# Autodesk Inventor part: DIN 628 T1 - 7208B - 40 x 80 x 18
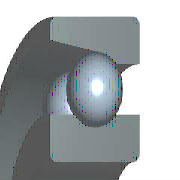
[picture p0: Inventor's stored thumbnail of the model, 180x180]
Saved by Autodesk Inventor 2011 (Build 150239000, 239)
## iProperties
IsCustomPart: 0
Created: 2009-02
Part Number: DIN 628 T1 - 7208B - 40 x 80 x 18
Material: Steel, Mild
Description: Angular Contact Ball Bearing
Document SubType Name: Modeling
Standard: DIN 628 T1
Designer: 904Chiaki
Standards Organization: DIN
Language: en-US
Size Designation: 7208B - 40 x 80 x 18
Categories: <MemberInstance><Categories><Category DisplayName="Shaft Parts" InternalName="7f7aeb1f-a693-4053-b835-cee3144e0d98" Mnemonic="SHFT"><Category DisplayName="Beari
Density: 1 g/cm^3
Author: 904Chiaki
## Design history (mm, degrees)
revolve "Body" stored, may be unused: angle "d9" = 90 deg
revolve "Ball" stored, may be unused: angle "d12" = 90 deg
pattern_circular "Balls" dims angle "d2" = 360 deg
body "Solid1"
sketch "Sketch" dims "d3" = 11.6 (= DDB)
  geometry: L1 (9, 24.2)-(9, 35.8); L2 (5.52, 34.64)-(0, 34.64); L3 (4.36, 26.52)-(0, 26.52); L4 (0, 20)-(18, 20); L5 (0, 40)-(18, 40); L6 (18, 20)-(18, 25.36); L7 (18, 33.48)-(18, 40); L8 (13.64, 33.48)-(18, 33.48); L9 (12.48, 25.36)-(18, 25.36); L10 (9, 30)-(14.8, 30); L11 (9, 30)-(3.2, 30); L12 (-3.6, 0)-(21.6, 0) reference; L13 (0, -3.4)-(0, 23.9) reference
  constraints: 22 end point, 4 point on line, 3 parallel, 2 perpendicular, 2 symmetric about line, 1 collinear, 1 midpoint, 10 other
  dimensions: "d8" = 53.04 diameter of L3 L12 (= KID1); "d10" = 40 diameter of L4 L12 (= WD); "d11" = 60 diameter of L10.start L12 (= DDA); "d13" = 69.28 diameter of L2 L12 (= DBB); "d15" = 50.72 diameter of L9 L12 (= DAC); "d16" = 66.96 diameter of L8 L12 (= KAD1); "d17" = 80 diameter of L5 L12 (= BD); "d18" = 18 distance between parallel lines of L13 L6 (= KB)
fillet "Fillet1" dims "d0" = 1.1 (= KRS), "d4" = 0.6 (= KR1S)
other parameters: "WD" = 40 [user parameter; used in 2 equation terms], "BD" = 80 [user parameter; used in 2 equation terms], "KB" = 18 [user parameter; used in 1 equation term], "KRS" = 1.1 [user parameter; used in 1 equation term], "KR1S" = 0.6 [user parameter; used in 1 equation term], "KID1" = 53.04 [user parameter; used in 1 equation term], "DAC" = 50.72 [user parameter; used in 1 equation term], "KAD1" = 66.96 [user parameter; used in 1 equation term], "DBB" = 69.28 [user parameter; used in 1 equation term], "DDA" = 60 [user parameter; used in 2 equation terms], "DDB" = 11.6 [user parameter; used in 2 equation terms], "d5" = 0, "d6" = 0, "d7" = 0, "d19" = 0, "d20" = 0, "BC" = 3.64e+07 [user parameter], "BC0" = 2.6e+07 [user parameter], "BBA" = 40 deg [user parameter]
